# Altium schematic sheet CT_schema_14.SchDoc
size 146 x 119 mm
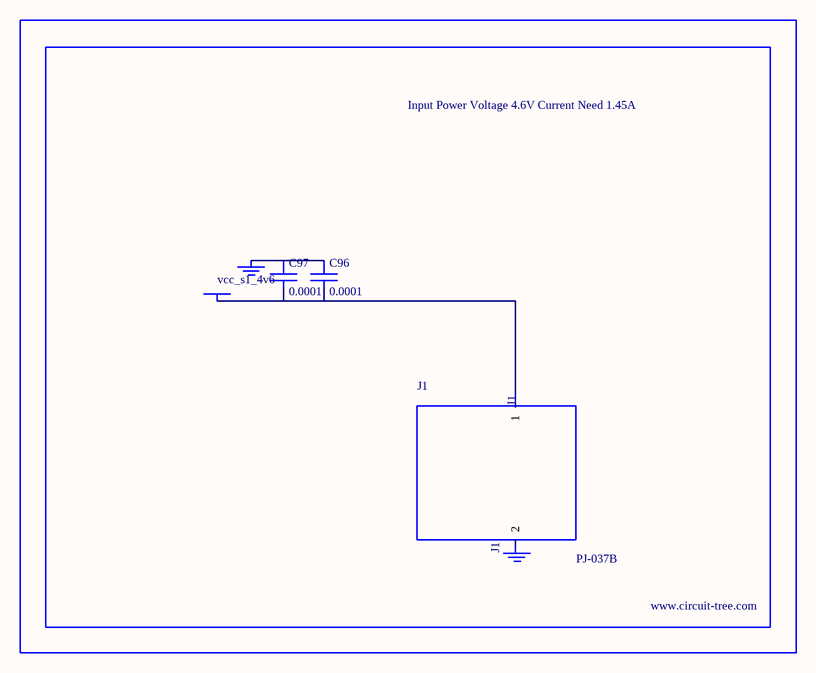
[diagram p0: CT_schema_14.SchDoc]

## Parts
BORDER13  (no value)
C96  0.0001  [EXV-9H]
C97  0.0001  [EXV-9H]
GND_INSTANCE_13_0  (no value)
GND_INSTANCE_13_1  (no value)
J1  PJ-037B  [PJ-037B_PACKAGE]
POWER_INSTANCE_13_0  vcc_s1_4v6

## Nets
NetC96_1: C96.1 C97.1 GND_INSTANCE_13_0.0(GND)
NetC96_2: C96.2 C97.2 J1.1 POWER_INSTANCE_13_0.0(PWR)

Not connected (* = marked no-connect by the designer): GND_INSTANCE_13_1 0(GND); J1 2

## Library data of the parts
BORDER13 = BORDER_PAGE13
C96 C97 = EDK107M035A9HAA
GND_INSTANCE_13_0 GND_INSTANCE_13_1 = GND
POWER_INSTANCE_13_0 = PWR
